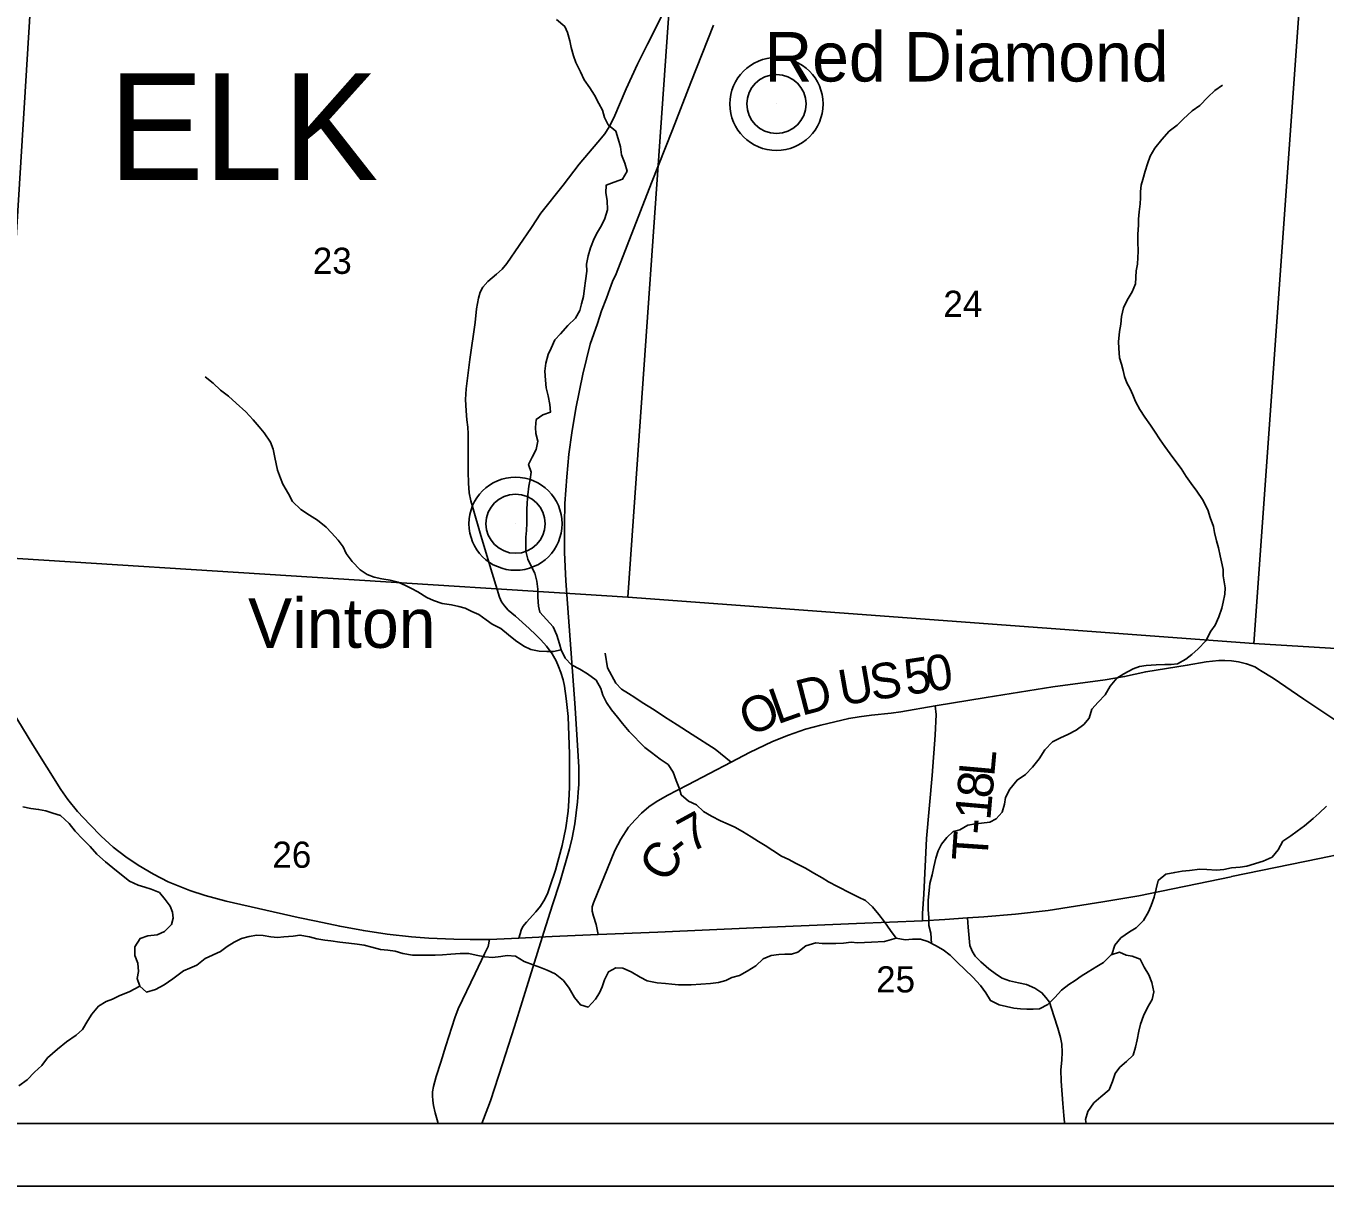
# Model space of a CAD drawing. Extents: x 0 to 34, y 0 to 22.
# Drawn here: x 24.565 to 26.642, y 14 to 15.854 of the extents above; entities that cross this region are included whole.
import ezdxf

# ---------------------------------------------------------------- set-up
doc = ezdxf.new("R2010")
doc.units = 0
for name, color, linetype in [('GM_X_County_Road', 7, 'Continuous'), ('GM_X_County_Road_Text', 7, 'Continuous'), ('GM_X_Minor_River', 7, 'Continuous'), ('GM_X_Rail_Line', 7, 'Continuous'), ('GM_X_Section', 7, 'Continuous'), ('GM_X_Section_Text', 7, 'Continuous'), ('GM_X_State_Route', 7, 'Continuous'), ('GM_X_Township_Road', 7, 'Continuous'), ('GM_X_Township_Road_Text', 7, 'Continuous'), ('GM_X_Township_Text', 7, 'Continuous'), ('GM_X_Unincorporated', 7, 'Continuous'), ('GM_X_Unincorporated_Location', 7, 'Continuous'), ('GM_X_Unincorporated_Text', 7, 'Continuous'), ('GM_X_US_Route', 7, 'Continuous'), ('SH_Data', 7, 'Continuous')]:
    doc.layers.add(name, color=color, linetype=linetype)

msp = doc.modelspace()

# ---------------------------------------------------------------- linework, layer by layer
at = {"layer": 'GM_X_County_Road'}
for points in [[(25.4796, 14.402), (25.4762, 14.4179), (25.4721, 14.4314), (25.47, 14.4391), (25.4699, 14.4459), (25.4719, 14.4526), (25.5064, 14.5362), (25.5157, 14.554), (25.5278, 14.5732), (25.5388, 14.5852), (25.5488, 14.5958), (25.5606, 14.606), (25.5721, 14.6138), (25.59, 14.6242), (25.6227, 14.6409), (25.6922, 14.6771), (25.7212, 14.6925), (25.7581, 14.7103), (25.7838, 14.7207), (25.811, 14.73), (25.8353, 14.7366), (25.8799, 14.7472), (25.8967, 14.75), (25.9161, 14.7523), (25.9475, 14.7556), (25.963, 14.7576), (26.0179, 14.7673), (26.0993, 14.7804), (26.2058, 14.7976), (26.2898, 14.809), (26.3207, 14.8141), (26.3543, 14.8217), (26.4206, 14.8323), (26.451, 14.8378), (26.4714, 14.8398), (26.4808, 14.8396), (26.4912, 14.8392), (26.5025, 14.8376), (26.5152, 14.8344), (26.5169, 14.8339), (26.5287, 14.8295), (26.5363, 14.8248)], [(26.5363, 14.8248), (26.5379, 14.8237), (26.5577, 14.8115), (26.6069, 14.7782), (26.6644, 14.7396), (26.7114, 14.7084), (26.7412, 14.6887), (26.7627, 14.6728), (26.7722, 14.6646), (26.7942, 14.6446), (26.8101, 14.6313), (26.8183, 14.6228), (26.8242, 14.6133), (26.8285, 14.6018), (26.8331, 14.5785), (26.8368, 14.566)], [(25.2238, 14.1), (25.2232, 14.102), (25.2192, 14.1168), (25.2164, 14.1289), (25.2155, 14.1369), (25.2148, 14.1439), (25.215, 14.1505), (25.2163, 14.1591), (25.2184, 14.1671), (25.2205, 14.1748), (25.228, 14.1977), (25.2362, 14.2238), (25.2505, 14.2687), (25.2561, 14.2833), (25.2828, 14.3396), (25.2982, 14.3712), (25.3036, 14.3825), (25.3057, 14.3939)]]:
    msp.add_lwpolyline(points, dxfattribs=at)
at = {"layer": 'GM_X_Minor_River'}
for points in [[(25.4615, 15.4618), (25.4608, 15.4729), (25.4634, 15.4862), (25.4671, 15.4991), (25.4731, 15.5139), (25.4784, 15.5241), (25.4848, 15.5348), (25.49, 15.5462), (25.4942, 15.5602), (25.4941, 15.5746), (25.4918, 15.5871), (25.4921, 15.5992), (25.505, 15.6042), (25.5186, 15.6088), (25.5261, 15.6217), (25.5223, 15.6346), (25.517, 15.6478), (25.515, 15.6607), (25.5116, 15.6732), (25.5078, 15.6857), (25.4956, 15.6959), (25.4899, 15.7073), (25.4865, 15.7194), (25.4807, 15.73), (25.4739, 15.7433), (25.4663, 15.7547), (25.4572, 15.7675), (25.4514, 15.7804), (25.4438, 15.7952), (25.44, 15.8058), (25.4365, 15.8194), (25.4342, 15.83), (25.4308, 15.8433), (25.4262, 15.8531), (25.4129, 15.8641)], [(26.339, 15.4624), (26.3413, 15.4732), (26.3416, 15.4838), (26.3423, 15.4933), (26.3419, 15.5096), (26.3419, 15.5213), (26.3426, 15.5357), (26.3429, 15.5452), (26.344, 15.5566), (26.3455, 15.5695), (26.3458, 15.579), (26.3462, 15.5892), (26.3473, 15.5991), (26.3499, 15.6086), (26.3536, 15.6218), (26.3574, 15.6332), (26.3615, 15.6457), (26.369, 15.6587), (26.38, 15.6723), (26.392, 15.6856), (26.4045, 15.6955), (26.4143, 15.7046), (26.4283, 15.718), (26.4407, 15.7267), (26.4536, 15.74), (26.4649, 15.7507), (26.477, 15.759)], [(25.4615, 15.4618), (25.4594, 15.4463), (25.4575, 15.4345), (25.456, 15.4213), (25.4529, 15.4095), (25.4503, 15.3989), (25.4431, 15.3868), (25.4313, 15.3751), (25.4196, 15.3618), (25.4105, 15.352), (25.4044, 15.3391), (25.3995, 15.3289), (25.3957, 15.3149), (25.3945, 15.302), (25.3952, 15.288), (25.3967, 15.2754), (25.3994, 15.2629), (25.4024, 15.2489), (25.4035, 15.2368), (25.391, 15.2323), (25.3804, 15.2247), (25.3792, 15.2122), (25.38, 15.2023), (25.383, 15.1902), (25.3803, 15.1769), (25.3742, 15.1648), (25.3685, 15.1531), (25.3727, 15.1406), (25.3711, 15.1292), (25.3689, 15.1182), (25.3673, 15.1046), (25.3662, 15.0917), (25.3654, 15.0803), (25.3654, 15.0591), (25.365, 15.0477), (25.3638, 15.0371), (25.3638, 15.0144), (25.3672, 15.0019), (25.3732, 14.9894), (25.3781, 14.9795), (25.3818, 14.9666), (25.383, 14.9537), (25.3833, 14.9412), (25.3841, 14.9268), (25.3863, 14.917), (25.3969, 14.9052), (25.4078, 14.8934), (25.4135, 14.8802), (25.418, 14.8665), (25.4202, 14.8567), (25.4267, 14.8434), (25.4368, 14.8331), (25.4501, 14.8259), (25.4625, 14.8183), (25.4761, 14.8081), (25.4837, 14.7952), (25.4871, 14.7842), (25.4927, 14.7728), (25.5006, 14.7607), (25.5105, 14.7493), (25.5184, 14.739), (25.529, 14.7261), (25.5542, 14.7007), (25.5648, 14.6927), (25.5784, 14.6821), (25.5916, 14.6734), (25.5992, 14.6612), (25.6041, 14.648), (25.6094, 14.6347), (25.6124, 14.6252), (25.6237, 14.615), (25.6365, 14.6089), (25.6479, 14.5986), (25.6607, 14.591), (25.6751, 14.5838), (25.6872, 14.5781), (25.6978, 14.5732), (25.7099, 14.5667), (25.7242, 14.558), (25.7355, 14.5507), (25.7465, 14.5443), (25.7586, 14.5359), (25.7726, 14.5272), (25.7839, 14.5215), (25.7949, 14.5158), (25.8107, 14.5078), (25.824, 14.4998), (25.8372, 14.4922), (25.8478, 14.4862), (25.8617, 14.4785), (25.8829, 14.4679), (25.8954, 14.4614), (25.9067, 14.4561), (25.918, 14.4459), (25.9279, 14.4337), (25.9369, 14.422), (25.9467, 14.4083), (25.9558, 14.3962), (25.9701, 14.3935), (25.9815, 14.3942), (25.9944, 14.3946)], [(26.338, 15.4415), (26.339, 15.4624)], [(26.0122, 14.3877), (26.011, 14.404), (26.008, 14.4162), (26.008, 14.4283), (26.0069, 14.442), (26.0066, 14.4567), (26.0077, 14.467), (26.0096, 14.4836), (26.0131, 14.4973), (26.0157, 14.5098), (26.0192, 14.5238), (26.023, 14.5355), (26.0283, 14.5461), (26.0366, 14.5567), (26.0468, 14.5666), (26.0574, 14.5692), (26.0703, 14.5764), (26.0824, 14.579), (26.0922, 14.5798), (26.1055, 14.5813), (26.1153, 14.5866), (26.1252, 14.5972), (26.1286, 14.6104), (26.1301, 14.621), (26.137, 14.6343), (26.1487, 14.6487), (26.1623, 14.6574), (26.1737, 14.6695), (26.1839, 14.6827), (26.1934, 14.6971), (26.2052, 14.7096), (26.2184, 14.7164), (26.2298, 14.7213), (26.243, 14.7285), (26.2555, 14.7376), (26.2638, 14.7474), (26.2684, 14.7618), (26.2782, 14.7731), (26.2896, 14.7849), (26.2976, 14.7989), (26.3082, 14.8118), (26.3195, 14.8182), (26.3343, 14.8265), (26.3442, 14.8303), (26.3551, 14.8318), (26.371, 14.8329), (26.385, 14.8332), (26.3948, 14.8332), (26.405, 14.8347), (26.4183, 14.8419), (26.4281, 14.8491), (26.438, 14.8585), (26.4505, 14.871), (26.4585, 14.8866), (26.4653, 14.8964), (26.471, 14.9097), (26.4759, 14.9233), (26.4782, 14.9328), (26.4805, 14.946), (26.4813, 14.9559), (26.4798, 14.9654), (26.4783, 14.9752), (26.4779, 14.9854), (26.4753, 14.9972), (26.4734, 15.007), (26.4708, 15.0199), (26.4674, 15.0309), (26.464, 15.0442), (26.4629, 15.0537), (26.4572, 15.0685), (26.4535, 15.0806), (26.4452, 15.0969), (26.4358, 15.1106), (26.4267, 15.1227), (26.4192, 15.1337), (26.4112, 15.1466), (26.4026, 15.1576), (26.3935, 15.1701), (26.3848, 15.1815), (26.3773, 15.1925), (26.3682, 15.2062), (26.3622, 15.2156), (26.3531, 15.2285), (26.3448, 15.2411), (26.338, 15.2536), (26.3339, 15.2642), (26.3294, 15.2737), (26.3241, 15.2835), (26.3207, 15.2938), (26.3181, 15.3033), (26.3154, 15.3131), (26.3124, 15.3237), (26.3113, 15.3389), (26.311, 15.3491), (26.3125, 15.3654), (26.3144, 15.3775), (26.3156, 15.3897), (26.319, 15.4033), (26.3247, 15.4154), (26.3327, 15.4287), (26.338, 15.4415)], [(25.4202, 14.8567), (25.4081, 14.8544), (25.3975, 14.8544), (25.3851, 14.8548), (25.3718, 14.8575), (25.3609, 14.8628), (25.3477, 14.8719), (25.3363, 14.881), (25.3239, 14.8909), (25.3103, 14.8978), (25.3004, 14.905), (25.2891, 14.9133), (25.2778, 14.9183), (25.2668, 14.9232), (25.257, 14.9263), (25.2453, 14.9285), (25.2305, 14.9308), (25.2165, 14.9354), (25.2056, 14.9403), (25.1916, 14.9495), (25.1814, 14.9548), (25.1716, 14.9597), (25.1602, 14.965), (25.1474, 14.9681), (25.1337, 14.9704), (25.1217, 14.9727), (25.1103, 14.9773), (25.0994, 14.9845), (25.0865, 14.9981), (25.0771, 15.0106), (25.0722, 15.0216), (25.0643, 15.0323), (25.0533, 15.0437), (25.045, 15.0531), (25.031, 15.0638), (25.0182, 15.0721), (25.0046, 15.0812), (24.9914, 15.0941), (24.9846, 15.1063), (24.9759, 15.1215), (24.9718, 15.1313), (24.9672, 15.1438), (24.965, 15.1541), (24.9631, 15.1643), (24.9601, 15.1776), (24.956, 15.1889), (24.9458, 15.2037), (24.9379, 15.2132), (24.9284, 15.2242), (24.9167, 15.2371), (24.9012, 15.2508), (24.8888, 15.2622), (24.8759, 15.2717), (24.8642, 15.2827), (24.8514, 15.2929)], [(24.5602, 14.6059), (24.573, 14.6033), (24.5855, 14.6017), (24.5969, 14.5994), (24.6082, 14.596), (24.6203, 14.5922), (24.6343, 14.5793), (24.6437, 14.5671), (24.6562, 14.5542), (24.6679, 14.5425), (24.6784, 14.5303), (24.6924, 14.5178), (24.7041, 14.5083), (24.7181, 14.4973), (24.7309, 14.4871), (24.7445, 14.481), (24.7551, 14.4775), (24.7653, 14.4741)], [(26.3001, 14.3698), (26.3052, 14.3847), (26.3147, 14.3964), (26.3287, 14.4062), (26.3389, 14.4127), (26.3507, 14.4244), (26.3586, 14.438), (26.3632, 14.4482), (26.3677, 14.4615), (26.3712, 14.4748), (26.3742, 14.488), (26.3867, 14.4982), (26.4007, 14.5012), (26.4124, 14.5031), (26.4245, 14.5042), (26.4408, 14.5061), (26.4522, 14.5057), (26.4673, 14.5045), (26.479, 14.5057), (26.4915, 14.5083), (26.5051, 14.5094), (26.5157, 14.5109), (26.5422, 14.5192), (26.5562, 14.5256), (26.5661, 14.537), (26.5736, 14.551), (26.5861, 14.5597), (26.5964, 14.5669), (26.6081, 14.5756), (26.6217, 14.5873), (26.6316, 14.596), (26.6433, 14.607)], [(24.7653, 14.4741), (24.7785, 14.4688), (24.788, 14.4578), (24.7955, 14.4472), (24.7993, 14.4377), (24.8008, 14.4282), (24.7981, 14.418), (24.7868, 14.4066), (24.775, 14.4013), (24.7603, 14.3998), (24.7478, 14.3957), (24.7391, 14.3821), (24.7391, 14.3684), (24.7443, 14.3559), (24.7451, 14.3426), (24.7432, 14.3317), (24.7473, 14.3195), (24.7579, 14.31), (24.7722, 14.3138), (24.7862, 14.3214), (24.7999, 14.3312), (24.8169, 14.3437), (24.8271, 14.3482), (24.8385, 14.3531), (24.8514, 14.3637), (24.8764, 14.375), (24.8866, 14.3826), (24.8979, 14.3894), (24.9097, 14.3955), (24.9218, 14.3989), (24.9343, 14.4011), (24.9441, 14.4003), (24.9566, 14.398), (24.9672, 14.3973), (24.9774, 14.3984), (24.9925, 14.3995), (25.0031, 14.401), (25.0182, 14.3983), (25.0299, 14.3949), (25.0428, 14.393), (25.0526, 14.3918), (25.067, 14.3899), (25.0814, 14.388), (25.0946, 14.3865), (25.1056, 14.3849), (25.1177, 14.3819), (25.1316, 14.3781), (25.1437, 14.3769), (25.1551, 14.3754), (25.1676, 14.3716), (25.1827, 14.3689), (25.219, 14.3689), (25.2311, 14.3696), (25.2443, 14.3707), (25.2591, 14.3714), (25.2727, 14.3714), (25.2848, 14.3688), (25.2984, 14.3661), (25.3109, 14.3653), (25.3238, 14.3668), (25.334, 14.3683), (25.3476, 14.3675), (25.3612, 14.3588), (25.3755, 14.3535), (25.3873, 14.3493), (25.3978, 14.3451), (25.4107, 14.339), (25.4239, 14.3284), (25.4334, 14.3159), (25.4416, 14.3014), (25.4511, 14.2893), (25.4636, 14.2859), (25.4753, 14.2984), (25.4817, 14.3086), (25.4859, 14.3184), (25.4897, 14.3294), (25.4962, 14.3423), (25.5079, 14.3487), (25.5189, 14.3479), (25.5325, 14.3422), (25.5465, 14.3339), (25.5578, 14.3278), (25.5737, 14.3247), (25.5869, 14.3236), (25.5975, 14.3228), (25.6081, 14.3217), (25.6281, 14.3216), (25.6436, 14.3224), (25.6588, 14.3235), (25.672, 14.325), (25.6834, 14.3284), (25.6932, 14.3333), (25.7053, 14.3363), (25.7174, 14.3431), (25.7314, 14.3518), (25.7432, 14.3628), (25.756, 14.3681), (25.7681, 14.3699), (25.778, 14.3703), (25.7886, 14.3703), (25.7984, 14.3737)], [(25.7984, 14.3737), (25.8113, 14.3839), (25.8272, 14.3884), (25.8374, 14.3876), (25.8593, 14.3876), (25.8714, 14.3883), (25.8839, 14.3895), (25.8941, 14.3887), (25.9051, 14.389), (25.9161, 14.3898), (25.9372, 14.3905), (25.9558, 14.3962)], [(25.9944, 14.3946), (26.0065, 14.3908), (26.0185, 14.3843), (26.031, 14.3775), (26.042, 14.3691), (26.0537, 14.357), (26.0654, 14.346), (26.0782, 14.3335), (26.0903, 14.3206), (26.099, 14.3088), (26.1061, 14.2963), (26.1201, 14.2894), (26.1439, 14.2841), (26.1542, 14.2829), (26.1644, 14.2825), (26.1746, 14.2825), (26.1848, 14.2829), (26.198, 14.2901), (26.209, 14.3011), (26.2196, 14.3132), (26.2314, 14.3222), (26.2416, 14.3283), (26.2514, 14.3351), (26.2624, 14.3423), (26.276, 14.3506), (26.287, 14.357), (26.2991, 14.3695), (26.3124, 14.3737), (26.323, 14.3687), (26.3328, 14.3672), (26.3457, 14.3626), (26.3521, 14.3497), (26.3592, 14.3372), (26.3641, 14.3251), (26.3675, 14.3103), (26.3645, 14.2978), (26.3572, 14.2853), (26.3508, 14.2717), (26.3462, 14.2584), (26.3436, 14.2474), (26.3405, 14.2334), (26.3379, 14.2217), (26.3341, 14.2092), (26.3238, 14.1989), (26.3128, 14.1899), (26.3053, 14.1796), (26.3015, 14.1668), (26.2961, 14.1539), (26.2825, 14.1425), (26.2715, 14.1327), (26.2617, 14.1191), (26.2582, 14.1062), (26.259, 14.1)], [(24.7473, 14.3195), (24.7303, 14.3101), (24.7151, 14.3044), (24.7038, 14.2987), (24.6935, 14.295), (24.6814, 14.2874), (24.6708, 14.2745), (24.664, 14.2643), (24.6557, 14.2503), (24.6454, 14.2409), (24.6303, 14.2303), (24.6159, 14.2185), (24.6, 14.2049), (24.5909, 14.1928), (24.5791, 14.1818), (24.5674, 14.1697), (24.5538, 14.1603)]]:
    msp.add_lwpolyline(points, dxfattribs=at)
at = {"layer": 'GM_X_Rail_Line'}
msp.add_lwpolyline([(25.2937, 14.1), (25.2965, 14.1067), (25.3076, 14.1362), (25.3267, 14.1951), (25.3457, 14.2548), (25.3824, 14.3732), (25.3925, 14.4058), (25.4065, 14.4491), (25.4182, 14.4852), (25.4338, 14.5388), (25.4381, 14.5563), (25.4422, 14.5788), (25.4446, 14.5964), (25.4466, 14.6138), (25.4478, 14.629), (25.4484, 14.6424), (25.4486, 14.6694), (25.4476, 14.687), (25.4427, 14.764), (25.4281, 14.9669), (25.4259, 15.0122), (25.4256, 15.0575), (25.4265, 15.0905), (25.4294, 15.1332), (25.4328, 15.1695), (25.4373, 15.2036), (25.4438, 15.2423), (25.455, 15.2973), (25.4668, 15.3452), (25.4784, 15.3784), (25.485, 15.3983), (25.4931, 15.4188), (25.4984, 15.4338), (25.5026, 15.4453), (25.5081, 15.4578), (25.5646, 15.603), (25.5981, 15.6877), (25.6278, 15.7636), (25.6638, 15.8551)], dxfattribs=at)
at = {"layer": 'GM_X_Section'}
for points in [[(25.5991, 15.9654), (25.5272, 14.9411), (24.518, 15.0047), (24.5822, 16.0431)], [(26.6015, 15.9112), (26.5271, 14.8668), (25.5272, 14.9411), (25.5991, 15.9654)], [(26.6015, 15.9112), (27.5892, 15.8592), (27.5781, 15.6831), (27.5261, 14.8062), (26.5271, 14.8668)]]:
    msp.add_lwpolyline(points, close=True, dxfattribs=at)
at = {"layer": 'GM_X_State_Route'}
msp.add_lwpolyline([(25.353, 14.396), (25.3548, 14.4032), (25.3564, 14.409), (25.3594, 14.4147), (25.3648, 14.4215), (25.3797, 14.4383), (25.3876, 14.4473), (25.3945, 14.4582), (25.3991, 14.4683), (25.4031, 14.4796), (25.4114, 14.5045), (25.4221, 14.5444), (25.428, 14.5725), (25.4317, 14.5991), (25.4328, 14.6156), (25.4337, 14.6372), (25.4337, 14.6901), (25.4314, 14.7503), (25.4285, 14.7793), (25.426, 14.7985), (25.4235, 14.8089), (25.42, 14.8206), (25.4164, 14.8304), (25.4123, 14.839), (25.4059, 14.8504), (25.3972, 14.8625), (25.3881, 14.8728), (25.3799, 14.8808), (25.3692, 14.891), (25.3473, 14.9106), (25.3359, 14.92), (25.3297, 14.9269), (25.325, 14.9334), (25.3217, 14.9412), (25.3062, 14.9914), (25.291, 15.0434), (25.2796, 15.0819), (25.2761, 15.0947), (25.2736, 15.1077), (25.2723, 15.123), (25.2718, 15.141), (25.2716, 15.2019), (25.2711, 15.2128), (25.2698, 15.2244), (25.2684, 15.2388), (25.2677, 15.2571), (25.2688, 15.2739), (25.2743, 15.3207), (25.2828, 15.3797), (25.2853, 15.4018), (25.2882, 15.419), (25.2912, 15.4284), (25.2953, 15.4361), (25.3031, 15.4454), (25.3169, 15.457), (25.3261, 15.4652), (25.3338, 15.4741), (25.373, 15.5316), (25.3877, 15.5544), (25.4234, 15.5991), (25.4494, 15.6329), (25.4788, 15.668), (25.49, 15.6814), (25.4971, 15.6928), (25.5048, 15.7067), (25.5242, 15.7535), (25.5422, 15.7929), (25.5585, 15.8248), (25.5986, 15.9056)], dxfattribs=at)
at = {"layer": 'GM_X_Township_Road'}
for points in [[(25.6922, 14.6771), (25.6664, 14.6981), (25.6298, 14.7216), (25.6058, 14.7371), (25.5853, 14.7495), (25.5692, 14.7608), (25.55, 14.7726), (25.5383, 14.7804), (25.5282, 14.787), (25.5169, 14.7937), (25.508, 14.8033), (25.4947, 14.8279), (25.4906, 14.8515)], [(26.0179, 14.7673), (26.0195, 14.7537), (26.0179, 14.7203), (26.0132, 14.656), (26.0042, 14.5552), (25.9999, 14.4662), (25.9975, 14.4354), (25.9975, 14.4238)], [(26.0697, 14.4283), (26.0709, 14.4136), (26.0723, 14.3959), (26.0736, 14.3845), (26.0769, 14.3752), (26.0819, 14.3674), (26.0909, 14.358), (26.1035, 14.3472), (26.1157, 14.3382), (26.1249, 14.3322), (26.1369, 14.3278), (26.1509, 14.3249), (26.1638, 14.3221), (26.1771, 14.3159), (26.1884, 14.3088), (26.195, 14.3014), (26.2008, 14.2936), (26.2077, 14.2722), (26.2137, 14.2524), (26.2183, 14.2373), (26.2201, 14.2267), (26.221, 14.2138), (26.2201, 14.2009), (26.2187, 14.1858), (26.2192, 14.1678), (26.2219, 14.132), (26.2233, 14.1127), (26.2247, 14.1016), (26.2251, 14.1)]]:
    msp.add_lwpolyline(points, dxfattribs=at)
at = {"layer": 'GM_X_Unincorporated'}
for centre, radius in [((25.7644, 15.7291), 0.0744), ((25.7644, 15.7291), 0.0472), ((25.3475, 15.0583), 0.0744), ((25.3475, 15.0583), 0.0472)]:
    msp.add_circle(centre, radius, dxfattribs=at)
at = {"layer": 'GM_X_Unincorporated_Location'}
for p, q in [((25.7644, 15.7291), (25.7644, 15.7291)), ((25.3475, 15.0583), (25.3475, 15.0583))]:
    msp.add_line(p, q, dxfattribs=at)
at = {"layer": 'GM_X_US_Route'}
for points in [[(24.5188, 14.7985), (24.5763, 14.705), (24.6211, 14.6336), (24.6324, 14.6177), (24.6476, 14.5985), (24.6676, 14.5776), (24.6857, 14.5593), (24.7049, 14.5417), (24.7248, 14.5259), (24.7446, 14.5125), (24.7692, 14.4984), (24.7926, 14.4863), (24.8272, 14.472), (24.8519, 14.4641), (24.8852, 14.4554), (25.0001, 14.4292), (25.0291, 14.4231)], [(25.4058, 14.3985), (25.4796, 14.402), (25.5747, 14.4056), (25.7283, 14.4124), (25.8924, 14.4195), (25.9975, 14.4238), (26.0336, 14.426), (26.0697, 14.4283), (26.0955, 14.4302), (26.1463, 14.4343), (26.1985, 14.4405), (26.2856, 14.4541), (26.3433, 14.4637), (26.4907, 14.4943), (26.4916, 14.4945), (26.6321, 14.5235), (26.8368, 14.566)], [(25.0291, 14.4231), (25.0667, 14.4151), (25.1046, 14.4081), (25.1423, 14.4027), (25.1813, 14.3981), (25.2089, 14.3961), (25.249, 14.3944), (25.275, 14.3939), (25.3057, 14.3939), (25.353, 14.396), (25.4058, 14.3985)]]:
    msp.add_lwpolyline(points, dxfattribs=at)
at = {"layer": 'SH_Data'}
for points in [[(23.4167, 21), (30.4167, 21), (30.4167, 14), (23.4167, 14)], [(23.5167, 20.9), (30.3167, 20.9), (30.3167, 14.1), (23.5167, 14.1)]]:
    msp.add_lwpolyline(points, close=True, dxfattribs=at)

# ---------------------------------------------------------------- texts
at = {"layer": 'GM_X_County_Road_Text'}
for s, rotation, p in [('0', 8.6292, (26.0075, 14.7895)), ('U', 9.9067, (25.8688, 14.7673)), ('S', 8.6616, (25.9177, 14.7759)), ('5', 8.6292, (25.9729, 14.7843)), ('D', 14.4842, (25.8045, 14.7512)), ('L', 19.5774, (25.7657, 14.7373)), ('O', 23.4014, (25.7207, 14.7178)), ('7', 28.581, (25.627, 14.5313)), ('C', 59.1494, (25.5905, 14.4822)), ('-', 38.5672, (25.6109, 14.5182))]:
    msp.add_text(s, height=0.0568, rotation=rotation, dxfattribs=at).set_placement(p)
at = {"layer": 'GM_X_Section_Text'}
for s, p in [('23', (25.0236, 15.4576)), ('24', (26.0311, 15.3888)), ('26', (24.959, 14.5085)), ('25', (25.9236, 14.3093))]:
    msp.add_text(s, height=0.04186, rotation=0, dxfattribs=at).set_placement(p)
at = {"layer": 'GM_X_Township_Road_Text'}
for s, rotation, p in [('L', 84.8932, (26.1122, 14.6531)), ('8', 84.9196, (26.1091, 14.6182)), ('1', 85.0242, (26.106, 14.5834)), ('-', 85.2169, (26.1041, 14.5602)), ('T', 86.0713, (26.1012, 14.518))]:
    msp.add_text(s, height=0.0568, rotation=rotation, dxfattribs=at).set_placement(p)
at = {"layer": 'GM_X_Township_Text'}
msp.add_text('ELK', height=0.17045, rotation=0, dxfattribs=at).set_placement((24.6974, 15.6076))
at = {"layer": 'GM_X_Unincorporated_Text'}
for s, height, p in [('Red Diamond', 0.078977, (25.7452, 15.765)), ('Vinton', 0.07898, (24.9202, 14.86))]:
    msp.add_text(s, height=height, rotation=0, dxfattribs=at).set_placement(p)

doc.saveas('drawing.dxf')
